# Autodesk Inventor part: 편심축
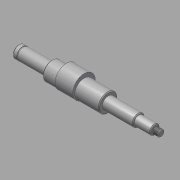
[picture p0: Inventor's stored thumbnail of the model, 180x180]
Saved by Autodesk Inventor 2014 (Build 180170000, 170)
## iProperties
Created: 2015-09
Part Number: 편심축
Material: 강철, 연강
Document SubType Name: Modeling
Designer: mduedu
Density: 1 g/cm^3
Appearance: Steel
Author: mduedu
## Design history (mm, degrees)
sketch "스케치1"
  geometry: L1 (-88.5, 0)-(88.5, 0); L2 (-88.5, 0)-(-88.5, 7.5); L3 (-88.5, 7.5)-(-47.35, 7.5); L4 (-47.35, 7.5)-(-47.35, 11.5); L5 (-47.35, 11.5)-(22.65, 11.5); L6 (22.65, 11.5)-(22.65, 7.5); L7 (22.65, 7.5)-(60.65, 7.5); L8 (60.65, 7.5)-(60.65, 6); L9 (60.65, 6)-(80.65, 6); L10 (80.65, 6)-(80.65, 3); L11 (80.65, 3)-(81.65, 3); L12 (81.65, 3)-(81.65, 4); L13 (81.65, 4)-(88.5, 4); L14 (88.5, 4)-(88.5, 0); 2 further points
  constraints: 28 end point, 10 parallel, 2 perpendicular, 1 coincident, 1 collinear, 1 horizontal, 1 midpoint
  dimensions: "d0" = 41.15 distance of L2.end L3.end; "d2" = 70 distance of L4.end L5.end; "d3" = 38 distance of L6.end L7.end; "d4" = 177 distance of L1.start L1.end; "d5" = 20 distance of L8.end L9.end; "d6" = 1 distance of L10.end L11.end; "d7" = 8 diameter of L13 L1; "d8" = 6 diameter of L11 L1; "d9" = 12 diameter of L9 L1; "d10" = 15 diameter of L7 L1; "d11" = 23 diameter of L5 L1; "d12" = 15 diameter of L3 L1
revolve "회전1" sketch "스케치1" stored, may be unused: angle "d13" = 90 deg
sketch "스케치2"
  geometry: L1 (-88.5, 7.5)-(-47.35, 7.5) reference; L2 (-88.5, -7.5)-(-88.5, 7.5) reference; L3 (88.5, -4)-(88.5, 4) reference; L4 (-88.5, 0)-(88.5, 0); L5 (-83.5, 7.5)-(-82.35, 7.5); L6 (-82.35, 7.5)-(-82.35, 7.15); L7 (-82.35, 7.15)-(-83.5, 7.15); L8 (-83.5, 7.15)-(-83.5, 7.5); 1 further point
  constraints: 10 end point, 2 midpoint, 2 parallel, 1 horizontal, 1 perpendicular, 1 point on line
  dimensions: "d14" = 5 distance between parallel lines of L8 L2; "d15" = 14.3 diameter of L7 L4; "d16" = 1.15 distance of L6.end L7.end
revolve "회전2" sketch "스케치2" stored, may be unused: angle "d17" = 90 deg
node "작업 평면1"
sketch "스케치3"
  geometry: C1 r 11.5 at (0, 0) reference; C2 r 14 at (0, 2.5); 1 further point
  constraints: 1 centre point, 1 tangent, 1 vertical alignment
  dimensions: "d19" = 28 diameter of C2
extrude "돌출1" join sketch "스케치3" distance "d21" = 22; taper "d22" = 0 deg
node "작업 평면2"
sketch "스케치4"
  geometry: L1 (10, 7.5)-(10, -7.5) reference; L2 (-10, 6)-(-10, -6) reference; L3 (10, 0)-(-10, 0); L4 (-5, -2)-(3, -2); L5 (3, 2)-(-5, 2); A1 r 2 centre (3, 0) between (3, -2) and (3, 2); A2 r 2 centre (-5, 0) between (-5, 2) and (-5, -2); 1 further point
  constraints: 6 end point, 4 point on circle, 4 tangent, 2 centre point, 2 midpoint, 2 parallel, 1 point on line
  dimensions: "d23" = 4 distance between parallel lines of L5 L4; "d25" = 12 dimension on A2 A1; "d26" = 3 distance edge to line of A2 L2
extrude "돌출2" cut sketch "스케치4" distance "d27" = 2.5; taper "d28" = 0 deg
chamfer "모따기1" distance "d29" = 1; stored, may be unused: second distance "d30" = 2, angle "d31" = 45 deg
feature "스레드1" dims "d32" = 10, "d33" = 0
chamfer "모따기2" distance "d34" = 1; stored, may be unused: second distance "d35" = 2, angle "d36" = 45 deg
chamfer "모따기3" distance "d37" = 1; stored, may be unused: second distance "d38" = 2, angle "d39" = 45 deg
node "솔리드1"
